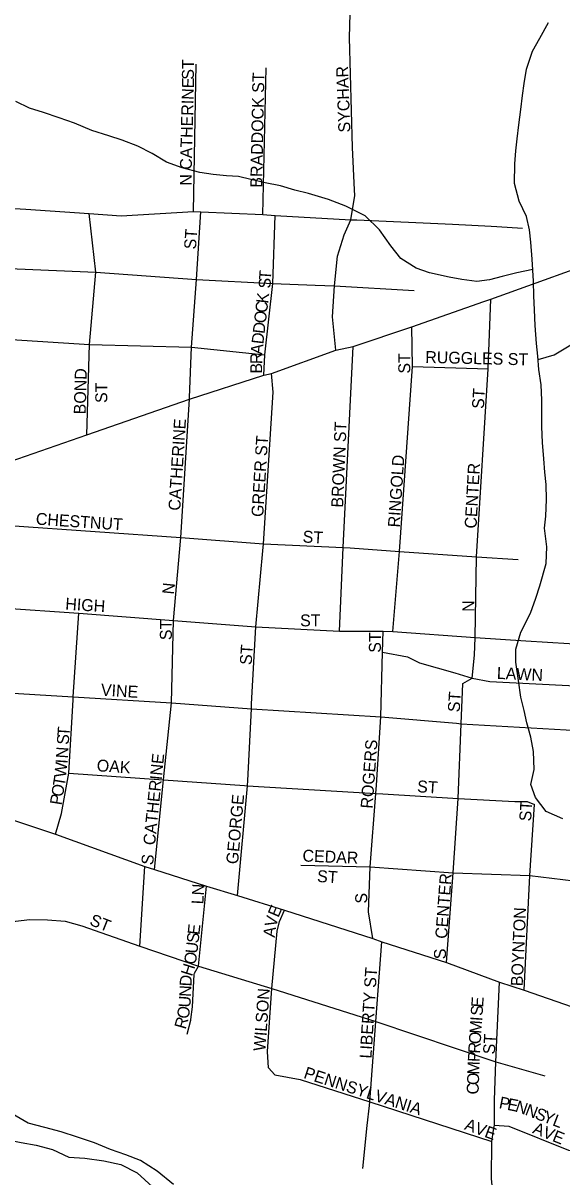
# Model space of a CAD drawing. Extents: x 1759416 to 2214760, y 252598 to 1116833.
# Drawn here: x 1975114 to 1977371, y 869319 to 874156 of the extents above; entities that cross this region are included whole.
import ezdxf

# ---------------------------------------------------------------- set-up
doc = ezdxf.new("R2010")
doc.units = 0
for name, color, linetype in [('GM_X_City_Street', 7, 'Continuous'), ('GM_X_City_Street_Text', 7, 'Continuous'), ('GM_X_Major_River', 7, 'Continuous'), ('GM_X_Minor_River', 7, 'Continuous'), ('GM_X_State_Route', 7, 'Continuous'), ('GM_X_US_Route', 7, 'Continuous')]:
    doc.layers.add(name, color=color, linetype=linetype)

msp = doc.modelspace()

# ---------------------------------------------------------------- linework, layer by layer
at = {"layer": 'GM_X_City_Street'}
for points in [[(1976501.9, 873456.4), (1976493.3, 873633.6), (1976480.9, 874095.9), (1976491.3, 874444.3), (1976493.4, 874498.4), (1976507.5, 874580.5), (1976654.1, 875014.9), (1976912.4, 875704.7)], [(1975827.2, 873366.6), (1975838.2, 873983.3)], [(1976118.1, 873353.9), (1976132.1, 873968.8)], [(1976423.9, 872783.9), (1976409.5, 872924.4), (1976418.5, 873054.1), (1976431.1, 873178.4), (1976458.1, 873268.4), (1976486.9, 873331.5), (1976503.1, 873432.6), (1976501.9, 873456.4)], [(1975018.7, 873383.3), (1975058, 873380.5), (1975102, 873377.5), (1975125.3, 873375.8)], [(1975125.3, 873375.8), (1975390.1, 873357.3), (1975524, 873347.9), (1975827.2, 873366.6), (1975858.1, 873365.1), (1976118.1, 873353.9), (1976170.1, 873349.7), (1976486.9, 873331.5), (1976511.7, 873330.4)], [(1975380.5, 872429.2), (1975392.3, 872808.3), (1975417.8, 873112), (1975390.1, 873357.3)], [(1975810.9, 872585.5), (1975819.5, 872797.8), (1975839.6, 873080.4), (1975858.1, 873365.1)], [(1976121.8, 872679.8), (1976126.1, 872765.2), (1976159.7, 873063.7), (1976170.1, 873349.7)], [(1976511.7, 873330.4), (1976911.9, 873313.5), (1977074, 873304.5), (1977098.7, 873302.8)], [(1972653.9, 873293.6), (1973000.8, 873267.3), (1973733.6, 873211.7), (1973745.3, 873210.8), (1974396.8, 873166.9), (1974782.2, 873141), (1975089.4, 873125.5), (1975417.8, 873112), (1975839.6, 873080.4), (1976159.7, 873063.7), (1976336.4, 873057.1)], [(1977098.7, 873302.8), (1977205.3, 873295.6)], [(1976336.4, 873057.1), (1976418.5, 873054.1), (1976751.6, 873034.2)], [(1977007.7, 871579.8), (1977013, 871918.8), (1977061.4, 872706.4), (1977072.2, 872998.2)], [(1972635.3, 872973), (1972980.9, 872936.8), (1973253.4, 872908.4), (1973460.5, 872886.7), (1973582.1, 872874), (1973706.6, 872871.7), (1973776.4, 872870.4), (1973975.9, 872866.6), (1974391.3, 872858.8), (1974759.3, 872851.9), (1975064.5, 872829.2), (1975392.3, 872808.3), (1975819.5, 872797.8), (1976126.1, 872765.2)], [(1976688.7, 871924.1), (1976690.2, 871941.2), (1976744.4, 872715.4), (1976742.6, 872882.9)], [(1976438.8, 871606.4), (1976454.7, 871957.3), (1976495.9, 872800.1)], [(1976744.4, 872715.4), (1977061.4, 872706.4)], [(1976117.6, 871943.1), (1976120.3, 871972.2), (1976161.3, 872608.3), (1976153.7, 872687.4)], [(1975743.9, 871650.6), (1975774.6, 871999.7), (1975810.7, 872579), (1975810.9, 872585.5)], [(1974366.1, 872071.6), (1974717.2, 872060.4), (1975056.5, 872049.5), (1975774.6, 871999.7), (1976120.3, 871972.2), (1976454.7, 871957.3), (1976483.9, 871955.3)], [(1976087.9, 871624.8), (1976117.6, 871943.1)], [(1976483.9, 871955.3), (1976690.2, 871941.2), (1977013, 871918.8)], [(1976662, 871605), (1976688.7, 871924.1)], [(1977013, 871918.8), (1977187, 871906.7)], [(1974361.8, 871738.5), (1974699.1, 871719.6), (1975021.6, 871704.8), (1975346.5, 871681.3), (1975743.9, 871650.6), (1976087.9, 871624.8), (1976438.8, 871606.4), (1976595.9, 871606.8)], [(1975322.9, 871318.9), (1975323.6, 871330.9), (1975346.5, 871681.3)], [(1975663.6, 870608), (1975702.1, 870983.8), (1975735.2, 871306.1), (1975743.9, 871650.6)], [(1976071, 871302.5), (1976087.9, 871624.8)], [(1976593.8, 870961.2), (1976612.5, 871247.2), (1976619.5, 871518), (1976621.8, 871606.9)], [(1976595.9, 871606.8), (1976621.8, 871606.9), (1976662, 871605), (1977007.7, 871579.8), (1977219.2, 871566.5)], [(1976887.8, 870217.1), (1976914.7, 870593), (1976935.7, 870904.4), (1976948.8, 871218.5), (1976955.9, 871387.5), (1976994.1, 871409.7), (1977004.4, 871506.6), (1977007.7, 871579.8)], [(1977219.2, 871566.5), (1977582.9, 871543.6)], [(1972917, 871489.2), (1973655.8, 871436.6), (1973998.9, 871420), (1974338.6, 871399.1), (1974672.9, 871375), (1975000.2, 871351.3), (1975323.6, 871330.9), (1975735.2, 871306.1), (1976069.8, 871281.2), (1976612.5, 871247.2), (1976928.4, 871220.2)], [(1976619.5, 871518), (1976724.4, 871498.3), (1976774.7, 871474.1), (1976921.6, 871431.8), (1976994.1, 871409.7), (1977068.6, 871395.6), (1977591.8, 871369.4), (1977869, 871356.9), (1977908.6, 871345.6), (1977923.7, 871311.6)], [(1975249.9, 870755), (1975274.6, 870842.7), (1975305.5, 871011.9), (1975322.9, 871318.9)], [(1976055.3, 870980.2), (1976069.8, 871281.2), (1976071, 871302.5)], [(1976928.4, 871220.2), (1976948.8, 871218.5), (1977584.2, 871181.1), (1977634.1, 871178.2), (1977916.5, 871163.1), (1978544.2, 871124.9)], [(1975305.5, 871011.9), (1975702.1, 870983.8), (1976041.5, 870959.6)], [(1976011.8, 870498.1), (1976054.2, 870958.7), (1976055.3, 870980.2)], [(1976041.5, 870959.6), (1976054.2, 870958.7), (1976591.6, 870926.5), (1976620.1, 870924.7)], [(1976578.2, 870317.4), (1976560.1, 870429.8), (1976567.9, 870618.1), (1976591.6, 870926.5), (1976593.8, 870961.2)], [(1976620.1, 870924.7), (1976935.7, 870904.4), (1977173.2, 870892.3), (1977225.5, 870892.3), (1977255.7, 870880.2)], [(1977212, 870101.6), (1977235.6, 870582.2), (1977255.7, 870880.2)], [(1975603.1, 870285.5), (1975624.1, 870620.3)], [(1976277.6, 870626), (1976567.9, 870618.1), (1976914.7, 870593), (1977235.6, 870582.2), (1977420, 870560)], [(1975830.8, 870166.8), (1975831.1, 870172.1), (1975849, 870202), (1975882.4, 870537.8)], [(1976141.9, 869775.9), (1976137.4, 869844.5), (1976155.3, 870108.4), (1976178.4, 870349.4), (1976187.4, 870389.1), (1976209.2, 870436.6)], [(1974984.7, 870365.7), (1975006.7, 870367.8), (1975083.3, 870390.2), (1975140.7, 870398.1), (1975216.5, 870396.7), (1975289.4, 870390.5), (1975359.8, 870370.8), (1975603.1, 870285.5), (1975849, 870202), (1976155.3, 870108.4), (1976591.4, 869969.5), (1976923.5, 869858.2), (1977093.9, 869800.5), (1977298.7, 869741.8)], [(1976564.1, 869617.5), (1976565.9, 869632.7), (1976591.4, 869969.5), (1976616.7, 870304.5)], [(1975816.3, 869978.6), (1975823.5, 870032), (1975830.8, 870166.8)], [(1977084.4, 869514.5), (1977087.7, 869535.3), (1977087.7, 869640.8), (1977093.9, 869800.5), (1977109.7, 870135.7)], [(1975800.6, 869917.6), (1975815.9, 869975.6), (1975816.3, 869978.6)], [(1976141.9, 869775.9), (1976167.8, 869746.9), (1976274.5, 869727.1), (1976565.9, 869632.7), (1977076.8, 869467.1)], [(1976537.2, 869353.8), (1976554.3, 869533.8), (1976564.1, 869617.5)], [(1977090.6, 869260.5), (1977080.5, 869270.6), (1977075.4, 869310.4), (1977076.8, 869467.1), (1977084.4, 869514.5)], [(1977087.7, 869535.3), (1977148.1, 869530.7), (1977397.6, 869431.1), (1977495.1, 869420.8)]]:
    msp.add_lwpolyline(points, dxfattribs=at)
at = {"layer": 'GM_X_Major_River'}
for points in [[(1975744, 869286.6), (1975675.8, 869342.9), (1975605.7, 869387.1), (1975543.5, 869411.3), (1975479.4, 869433.5), (1975413.2, 869461.7), (1975341, 869485.9), (1975272.8, 869508), (1975204.6, 869526.2), (1975134.4, 869544.4), (1975084.3, 869572.6), (1975012.2, 869618.8), (1974946, 869643)], [(1974634.8, 869561.2), (1974684.9, 869549.1), (1974751.1, 869533), (1974827.3, 869520.8), (1974893.5, 869504.6), (1974961.7, 869490.5), (1975036, 869476.3), (1975106.2, 869462.2), (1975168.4, 869452), (1975236.5, 869433.9), (1975304.7, 869401.7), (1975372.9, 869397.5), (1975451.2, 869385.4), (1975523.4, 869371.2), (1975591.5, 869335), (1975655.6, 869276.7)]]:
    msp.add_lwpolyline(points, dxfattribs=at)
at = {"layer": 'GM_X_Minor_River'}
for points in [[(1977192.1, 873409.4), (1977172.5, 873483.6), (1977173, 873565.8), (1977177.4, 873619.8), (1977183.7, 873669.9), (1977190.1, 873729.9), (1977198.5, 873794), (1977204.9, 873852), (1977213.2, 873902), (1977221.6, 873962.1), (1977248.1, 874038), (1977278.5, 874091.9), (1977314.9, 874157.8)], [(1977249.2, 873122.7), (1977182.2, 873109), (1977120, 873093.3), (1977067.9, 873079.7), (1977013.8, 873072), (1976951.8, 873080.4), (1976897.8, 873090.8), (1976815.8, 873109.3), (1976759.9, 873127.7), (1976696.1, 873168.2), (1976654.4, 873222.5), (1976606.8, 873288.9), (1976547.1, 873347.4), (1976465.3, 873388), (1976393.4, 873416.5), (1976309.4, 873441), (1976251.5, 873455.4), (1976191.5, 873473.8), (1976127.5, 873486.3), (1976067.6, 873500.7), (1976015.6, 873513), (1975965.6, 873515.4), (1975909.6, 873521.7), (1975853.6, 873530.1), (1975779.6, 873548.6), (1975713.7, 873573.1), (1975653.9, 873609.5), (1975594, 873639.9), (1975528.1, 873664.4), (1975472.2, 873682.8), (1975402.2, 873705.2), (1975328.4, 873735.8), (1975264.5, 873758.2), (1975198.5, 873780.7), (1975140.6, 873799.1), (1975082.7, 873827.5)], [(1977373.9, 870820.1), (1977304, 870850.6), (1977260.3, 870909), (1977240.6, 870963.2), (1977255.1, 871027.2), (1977251.5, 871101.4), (1977239.9, 871161.5), (1977224.3, 871221.7), (1977212.6, 871273.9), (1977198.9, 871330.1), (1977189.4, 871400.2), (1977177.8, 871476.4), (1977178.2, 871530.5), (1977198.6, 871602.5), (1977239.2, 871682.3), (1977261.6, 871744.3), (1977278, 871796.3), (1977304.6, 871890.3), (1977307, 871960.4), (1977297.5, 872038.5), (1977303.8, 872088.6), (1977306.3, 872158.7), (1977304.7, 872220.8), (1977299, 872272.9), (1977295.3, 872329), (1977289.8, 872397.2), (1977286.2, 872463.3), (1977286.9, 872575.5), (1977283.3, 872639.6), (1977273.7, 872703.8), (1977270, 872759.9), (1977264.4, 872812), (1977258.8, 872888.1), (1977255.3, 872954.3), (1977253.6, 873012.4), (1977252, 873074.5), (1977246.6, 873166.7), (1977241, 873236.8), (1977235.3, 873288.9), (1977221.7, 873345.1), (1977192.1, 873409.4)], [(1977271, 872745), (1977338.1, 872765.4), (1977408.5, 872807.1)]]:
    msp.add_lwpolyline(points, dxfattribs=at)
at = {"layer": 'GM_X_State_Route'}
msp.add_lwpolyline([(1972869.6, 871157.2), (1973322.3, 871123.7), (1973630.8, 871099.6), (1973977.1, 871084.7), (1974317.9, 871056.2), (1974634.9, 870951.4), (1974972, 870847.6), (1975249.9, 870755), (1975624.1, 870620.3), (1975663.6, 870608), (1975882.4, 870537.8), (1976011.8, 870498.1), (1976209.2, 870436.6), (1976578.2, 870317.4), (1976616.7, 870304.5), (1976887.8, 870217.1), (1977109.7, 870135.7), (1977212, 870101.6), (1977513.8, 869997.3)], dxfattribs=at)
at = {"layer": 'GM_X_US_Route'}
for points in [[(1977044.2, 872988.4), (1977072.2, 872998.2), (1977607.9, 873191.4)], [(1974463.6, 872107), (1974724.7, 872201.7), (1975059.8, 872317.5), (1975380.5, 872429.2), (1975810.7, 872579), (1976121.8, 872679.8), (1976153.7, 872687.4), (1976423.9, 872783.9), (1976495.9, 872800.1), (1976742.6, 872882.9), (1977044.2, 872988.4)]]:
    msp.add_lwpolyline(points, dxfattribs=at)

# ---------------------------------------------------------------- texts
at = {"layer": 'GM_X_City_Street_Text'}
for s, rotation, p in [('ST', 90, (1975829, 873918.5)), ('SYCHAR', 92.0442, (1976484.6, 873698.1)), ('CATHERINE', 88.5506, (1975820.2, 873540.3)), ('BRADDOCK ST', 88.8293, (1976115, 873465.5)), ('N', 90, (1975820.2, 873474)), ('ST', 86.4262, (1975837.8, 873206.2)), ('S', 88.0599, (1976150.2, 873042.4)), ('T', 85.9806, (1976151.3, 873077.1)), ('C', 83.3299, (1976135.1, 872939)), ('K', 83.3447, (1976139.7, 872978.4)), ('O', 83.3412, (1976130, 872895.3)), ('D', 83.3629, (1976124.9, 872851.6)), ('D', 83.3629, (1976119.8, 872807.9)), ('A', 84.5938, (1976115.7, 872764.4)), ('R', 88.9314, (1976115, 872725.8)), ('ST', 90, (1976735.4, 872686.4)), ('RUGGLES ST', 358.6342, (1976797.8, 872731.1)), ('BOND', 88.5319, (1975375.8, 872515.1)), ('B', 89.8785, (1976115, 872686.4)), ('ST', 90, (1975466.2, 872563.2)), ('ST', 86.4262, (1977043.4, 872537.4)), ('CATHERINE', 86.3778, (1975771.8, 872110.6)), ('BROWN ST', 87.5787, (1976453.8, 872123.7)), ('GREER ST', 86.477, (1976119.4, 872084.2)), ('RINGOLD', 86.3071, (1976691.4, 872040.3)), ('CENTER', 86.822, (1977012.6, 872035.8)), ('CHESTNUT', 356.0838, (1975165.8, 872053.5)), ('ST', 356.4262, (1976283.4, 871978.7)), ('N', 84.2916, (1975745.4, 871759)), ('HIGH', 356.1817, (1975289.2, 871697)), ('N', 90, (1977003.8, 871687.7)), ('ST', 90, (1975736.6, 871568.9)), ('ST', 0, (1976274, 871626.7)), ('ST', 90, (1976612.2, 871516.1)), ('ST', 86.4262, (1976071, 871463.8)), ('LAWN', 357.2752, (1977097.2, 871406.7)), ('VINE', 356.5338, (1975438.5, 871336.2)), ('ST', 86.4118, (1976942.2, 871265.8)), ('T', 86.1714, (1975306.8, 871164.3)), ('S', 86.2021, (1975304.5, 871129.1)), ('ROGERS', 85.7315, (1976577, 870861.4)), ('N', 86.1982, (1975300.7, 871072)), ('W', 84.1549, (1975293.2, 870991.2)), ('I', 86.167, (1975299.2, 871050)), ('OAK', 356.1883, (1975421, 871019.4)), ('CATHERINE', 84.2179, (1975666.2, 870707.4)), ('O', 80.8683, (1975280.3, 870909.9)), ('T', 80.8832, (1975287.2, 870953.4)), ('ST', 356.4118, (1976763, 870931.4)), ('P', 80.8924, (1975274.7, 870875.2)), ('GEORGE', 84.8967, (1976013.8, 870628.1)), ('ST', 86.4254, (1977241.4, 870808.2)), ('S', 82.8783, (1975657.4, 870624)), ('CEDAR', 357.5647, (1976283.2, 870641.1)), ('ST', 356.4254, (1976344, 870555.2)), ('CENTER', 85.766, (1976889.4, 870315.6)), ('LN', 86.8222, (1975868.6, 870460.6)), ('S', 90, (1976555, 870464.5)), ('E', 66.7727, (1976182.7, 870403.3)), ('BOYNTON', 87.4753, (1977206.2, 870117.3)), ('ST', 338.2086, (1975388.7, 870376.4)), ('E', 83.7865, (1975852, 870331.8)), ('V', 76.812, (1976173.3, 870362.7)), ('S', 83.7865, (1975848.2, 870296.8)), ('A', 82.4819, (1976167.8, 870320.3)), ('U', 83.9093, (1975843.5, 870253.1)), ('O', 80.3658, (1975835.7, 870206.3)), ('S', 90, (1976885, 870231.3)), ('H', 72.526, (1975820.7, 870157.1)), ('LIBERTY ST', 86.3325, (1976572.6, 869813.7)), ('D', 87.1572, (1975819.1, 870116.5)), ('N', 87.1781, (1975817, 870072.6)), ('WILSON', 85.8427, (1976128.2, 869844.7)), ('U', 86.3107, (1975814.1, 870027.8)), ('S', 86.2021, (1977038, 869992.7)), ('E', 86.1732, (1977040.4, 870027.8)), ('R', 74.2081, (1975794.2, 869935)), ('O', 80.6492, (1975806.3, 869979)), ('I', 86.151, (1977036.6, 869970.7)), ('M', 86.1908, (1977033.1, 869918)), ('O', 86.1982, (1977030.1, 869874.1)), ('ST', 86.4254, (1977089.7, 869831.3)), ('P', 87.6493, (1977026.1, 869799.8)), ('R', 86.1843, (1977027.5, 869834.6)), ('M', 88.0435, (1977024.3, 869747.1)), ('PENNSYLVANIA', 342.0727, (1976285.7, 869734.2)), ('O', 88.0108, (1977022.7, 869703.1)), ('C', 88.0326, (1977021.4, 869663.5)), ('P', 348.6151, (1977104.3, 869607.2)), ('E', 348.6151, (1977138.8, 869600.3)), ('N', 341.4959, (1977171.7, 869593.8)), ('N', 339.0143, (1977212.9, 869580)), ('S', 339.0155, (1977254, 869564.2)), ('AVE', 339.6777, (1976959.2, 869518.5)), ('Y', 339.0064, (1977286.9, 869551.6)), ('L', 339.0168, (1977327.9, 869535.9)), ('AVE', 337.838, (1977244.5, 869503.7))]:
    msp.add_text(s, height=50, rotation=rotation, dxfattribs=at).set_placement(p)

doc.saveas('drawing.dxf')
